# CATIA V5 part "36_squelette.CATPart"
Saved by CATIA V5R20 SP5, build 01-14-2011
Part number: 36_squelette
Publications: "Point.1", "Plan.5", "Plan.6", "Point.3", "diametre_36", "Point.4"
Bounding box of the stored display mesh (mm): x 0 to 0, y 33.362 to 43.362, z -155.5 to -155.5
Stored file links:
  C:\Documents and Settings\anizard\Bureau\13\36_squelette.CATPart
  C:\Documents and Settings\anizard\Bureau\13\anizard.CATProduct
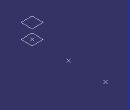
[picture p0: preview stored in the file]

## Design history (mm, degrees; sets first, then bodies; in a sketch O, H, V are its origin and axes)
Parameters
  diametre_36 = 20 mm
Set1
  Line1: linked copy from another document
  Point1: linked copy from another document
Body1 (main body)
  Point2: type OnCurve, Support Line1, RefPoint Point1, Length 0
  Plane1: type Normal, Curve Line1, RefPoint Point2
  Plane2: type Offset, RefPlane Plane1, Offset 2, reversed
  Point3: (0, 5, 0), relative to Point2
  Point4: (0, 10 {= diametre_36 /2}, 0), relative to Point2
